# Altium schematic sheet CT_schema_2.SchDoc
size 276 x 169 mm
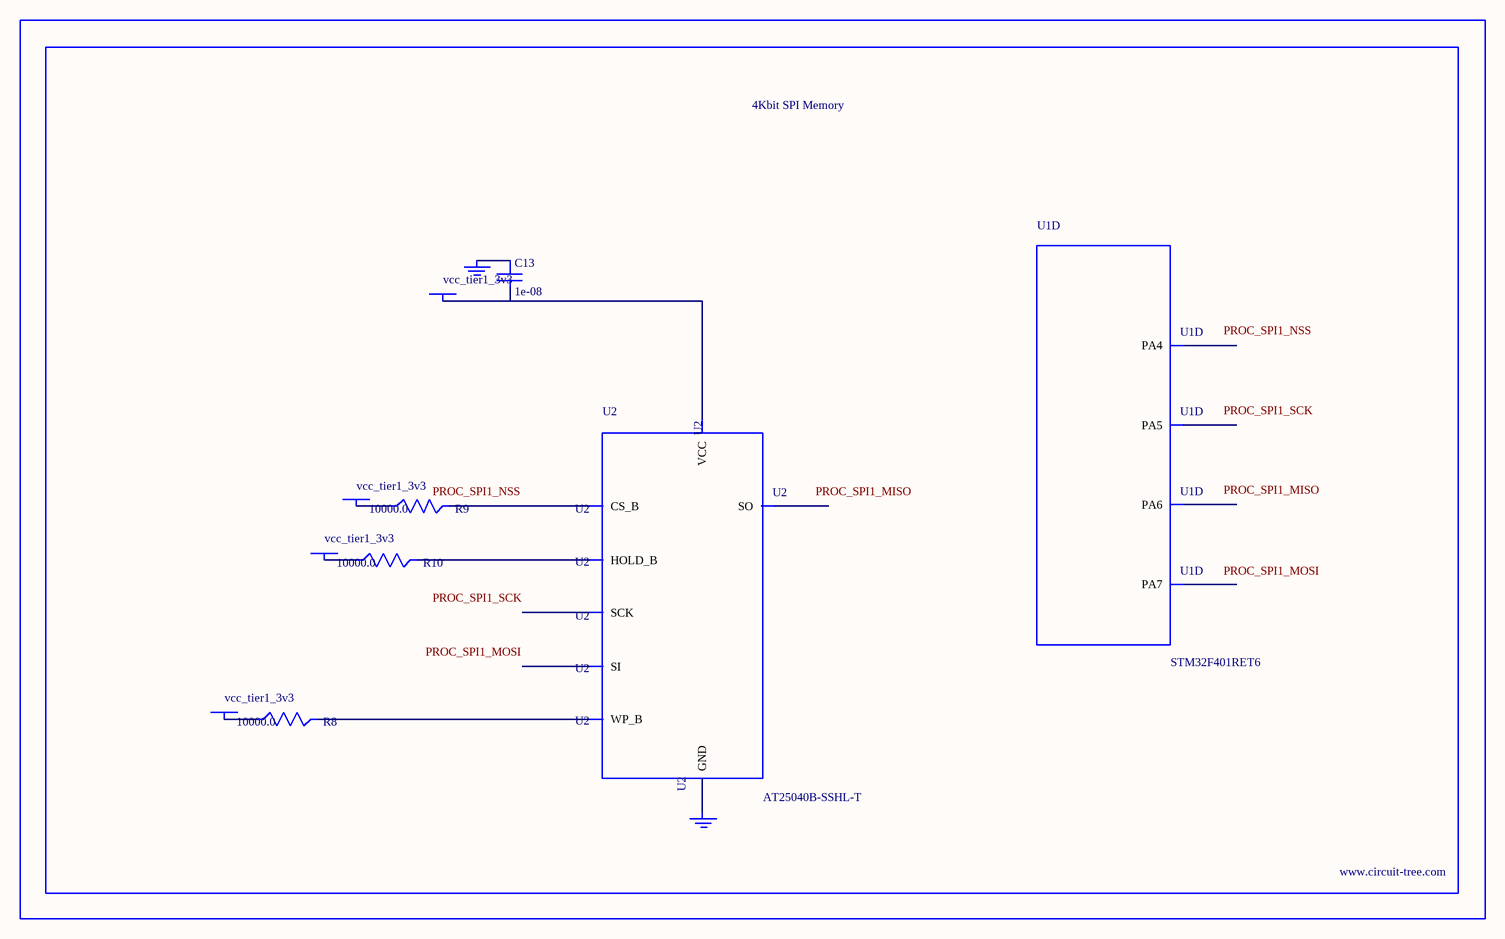
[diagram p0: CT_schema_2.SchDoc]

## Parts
BORDER1  (no value)
C13  1e-08  [C0402]
GND_INSTANCE_1_0  (no value)
GND_INSTANCE_1_1  (no value)
POWER_INSTANCE_1_0  vcc_tier1_3v3
POWER_INSTANCE_1_1  vcc_tier1_3v3
POWER_INSTANCE_1_2  vcc_tier1_3v3
POWER_INSTANCE_1_3  vcc_tier1_3v3
R8  10000.0  [R0603]
R9  10000.0  [R0603]
R10  10000.0  [R0603]
U1  STM32F401RET6  [LQFP64]  (part D of 7)
U2  AT25040B-SSHL-T  [SOIC-8]

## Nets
NetC13_1: C13.1 GND_INSTANCE_1_0.0(GND)
NetC13_2: C13.2 POWER_INSTANCE_1_3.0(PWR) U2.8(VCC)
NetGND_INSTANCE_1_1_0: GND_INSTANCE_1_1.0(GND) U2.4(GND)
NetPOWER_INSTANCE_1_0_0: POWER_INSTANCE_1_0.0(PWR) R9.1
NetPOWER_INSTANCE_1_1_0: POWER_INSTANCE_1_1.0(PWR) R8.1
NetPOWER_INSTANCE_1_2_0: POWER_INSTANCE_1_2.0(PWR) R10.1
NetR8_2: R8.2 U2.3(WP_B)
NetR9_2: R9.2 U2.1(CS_B)
NetR10_2: R10.2 U2.7(HOLD_B)

Not connected (* = marked no-connect by the designer): U1 20(PA4) 21(PA5) 22(PA6) 23(PA7); U2 2(SO) 5(SI) 6(SCK)

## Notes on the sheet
- Labels drawn without touching a wire or pin: PROC_SPI1_MISO, PROC_SPI1_MOSI, PROC_SPI1_NSS, PROC_SPI1_SCK

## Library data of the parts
BORDER1 = BORDER_PAGE1
C13 = C0402C103K3RAC
GND_INSTANCE_1_0 GND_INSTANCE_1_1 = GND
POWER_INSTANCE_1_0-POWER_INSTANCE_1_3 = PWR
R8-R10 = RC0603JR-0710KL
